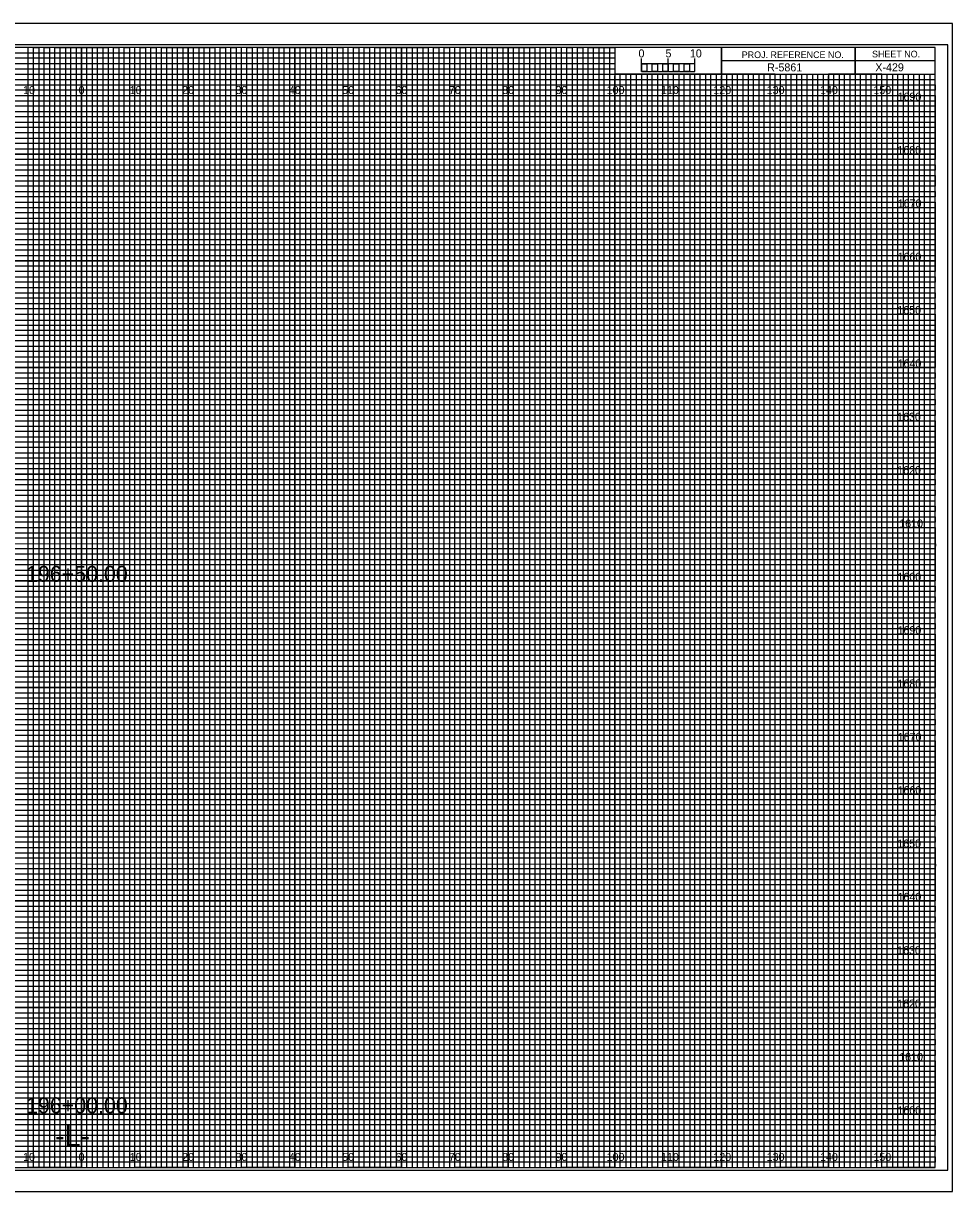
# Model space of a CAD drawing. Extents: x -13 to 323, y -5 to 6154.
# Drawn here: x 149.1 to 323.3, y 5495.5 to 5714.5 of the extents above; entities that cross this region are included whole.
import ezdxf

# ---------------------------------------------------------------- set-up
doc = ezdxf.new("R2010")
doc.units = 0
for name, color, linetype in [('Exist CMT Ground Line', 7, 'Continuous'), ('Prop Horizontal Alignment', 7, 'Continuous'), ('Prop Retaining Wall', 7, 'Continuous'), ('Prop XS Alignment Label', 7, 'Continuous'), ('Prop XS Bar Scale Labels', 7, 'Continuous'), ('Prop XS DDE', 7, 'Continuous'), ('Prop XS DDE Elevations', 7, 'Continuous'), ('Prop XS DDE Slope Text', 7, 'Continuous'), ('Prop XS Earthwork Shape', 7, 'Continuous'), ('Prop XS Elevation Labels', 7, 'Continuous'), ('Prop XS Project Number', 7, 'Continuous'), ('Prop XS Sheet Number', 7, 'Continuous'), ('Prop XS Station Labels', 7, 'Continuous'), ('Raster_Level_0', 7, 'Continuous'), ('Scratch_Level_3', 7, 'Continuous'), ('Sheet Cutting Line CELL', 7, 'Continuous')]:
    doc.layers.add(name, color=color, linetype=linetype)

msp = doc.modelspace()

# ---------------------------------------------------------------- linework, layer by layer
at = {"layer": 'Exist CMT Ground Line'}
for p, q in [((265, 5705.49), (265, 5707.9)), ((265, 5706.9), (265, 5707.9)), ((270, 5705.49), (270, 5707.9)), ((275, 5705.49), (275, 5707.9)), ((275, 5706.9), (275, 5707.9))]:
    msp.add_line(p, q, dxfattribs=at)
for points in [[(275, 5706.9), (265, 5706.9), (265, 5705.49), (275, 5705.49)], [(265, 5706.9), (266, 5706.9), (266, 5705.49), (265, 5705.49)], [(267, 5706.9), (268, 5706.9), (268, 5705.49), (267, 5705.49)], [(269, 5706.9), (270, 5706.9), (270, 5705.49), (269, 5705.49)], [(271, 5706.9), (272, 5706.9), (272, 5705.49), (271, 5705.49)], [(273, 5706.9), (274, 5706.9), (274, 5705.49), (273, 5705.49)]]:
    msp.add_lwpolyline(points, close=True, dxfattribs=at)
at = {"layer": 'Prop Retaining Wall'}
for p, q in [((0, 5709), (260, 5709)), ((260, 5707.98), (0, 5707.98)), ((260, 5709), (260, 5707.98)), ((0, 5707), (260, 5707)), ((260, 5705.89), (0, 5705.89)), ((260, 5707), (260, 5705.89)), ((0, 5704), (320, 5704))]:
    msp.add_line(p, q, dxfattribs=at)
for points in [[(0, 5703), (270, 5703), (320, 5703), (320, 5702), (0, 5702)], [(0, 5701), (320, 5701), (320, 5699), (0, 5699)], [(0, 5698), (320, 5698), (320, 5697), (0, 5696.98)], [(0, 5696), (320, 5696), (320, 5694), (0, 5694)], [(0, 5693), (320, 5693), (320, 5692), (0, 5692)], [(0, 5691), (320, 5691), (320, 5689), (0, 5689)], [(0, 5688), (320, 5688), (320, 5687), (0, 5687)], [(0, 5686), (320, 5686), (320, 5684), (0, 5684)], [(0, 5683), (320, 5683), (320, 5682), (0, 5682)], [(0, 5681), (320, 5681), (320, 5679), (0, 5679)], [(0, 5678), (320, 5678), (320, 5677), (0, 5677)], [(0, 5676), (320, 5676), (320, 5673.95), (320, 5673), (320, 5672), (0, 5672)], [(0, 5674), (320, 5674), (320, 5673), (0, 5673)], [(0, 5671), (320, 5671), (320, 5669), (0, 5669.03)], [(0, 5669.03), (320, 5669), (320, 5668), (0, 5668)], [(0, 5667), (320, 5667), (320, 5666), (0, 5666)], [(0, 5664), (320, 5664), (320, 5663), (0, 5663)], [(0, 5662), (320, 5662), (320, 5661), (0, 5661)], [(-0.07, 5658.89), (320, 5658.89), (320, 5657.88), (-0.07, 5657.88)], [(0, 5657), (320, 5657), (320, 5656), (0, 5656)], [(0, 5654), (320, 5654), (320, 5653), (0, 5653)], [(0, 5652), (320, 5652), (320, 5651), (0, 5651)], [(0, 5649), (320, 5649), (320, 5648), (0, 5648)], [(0, 5647), (320, 5647), (320, 5646), (0, 5646)], [(0, 5644), (320, 5644), (320, 5643), (0, 5643)], [(0, 5642), (320, 5642), (320, 5641), (0, 5641)], [(0, 5639), (320, 5639), (319.99, 5637.98), (0, 5638)], [(0, 5637), (320, 5637), (320, 5636), (0, 5636)], [(0, 5634), (320, 5634), (320, 5633), (0, 5633)], [(0, 5632), (320, 5632), (320, 5631), (0, 5631)], [(0, 5629), (320, 5629), (320, 5628), (0, 5628)], [(0, 5627), (320, 5627), (320, 5626), (0, 5626)], [(0, 5624), (320, 5624), (320, 5623), (0, 5623)], [(0, 5622), (320, 5622), (320, 5621), (0, 5621)], [(0, 5619), (320, 5619), (320, 5618), (0, 5618)], [(0, 5616.99), (320.07, 5616.91), (320, 5616), (0, 5616)], [(0, 5614), (320, 5614), (320, 5613), (0, 5613)], [(0, 5612), (320, 5612), (320, 5611), (0, 5611)], [(0, 5609), (320, 5609), (320, 5608), (0, 5608)], [(0, 5607), (320, 5607), (320, 5606), (0, 5606)], [(0, 5604), (320, 5604), (320, 5603), (0, 5603)], [(0, 5602), (320, 5602), (320, 5601), (0, 5601)], [(0, 5599), (320, 5599), (320, 5598), (0, 5598)], [(0, 5597), (320, 5597), (320, 5596), (0, 5596)], [(0, 5594), (320, 5594), (320, 5593), (0, 5593)], [(0, 5592), (320, 5592), (320, 5591), (0, 5591)], [(0, 5589), (320, 5589), (320, 5588), (0, 5588)], [(0, 5587), (320, 5587), (320, 5586), (0, 5586)], [(0, 5584), (320, 5584), (320, 5583), (0, 5583)], [(0, 5582), (320, 5582), (320, 5581), (0, 5581)], [(0, 5579), (320, 5579), (319.99, 5577.98), (0, 5578)], [(0, 5577), (320, 5577), (320, 5576), (0, 5576)], [(0, 5574), (320, 5574), (320, 5573), (0, 5573)], [(0, 5572), (320, 5572), (320, 5571), (0, 5571)], [(0, 5569), (320, 5569), (320, 5568), (0, 5568)], [(0, 5567), (320, 5567), (320, 5566), (0, 5566)], [(0, 5564), (320, 5564), (320, 5563), (0, 5563)], [(0, 5562), (320, 5562), (320, 5561), (0, 5561)], [(0, 5559), (320, 5559), (320, 5558), (0, 5558)], [(0, 5556.99), (320.07, 5556.91), (320, 5556), (0, 5556)], [(0, 5554), (320, 5554), (320, 5553), (0, 5553)], [(0, 5552), (320, 5552), (320, 5551), (0, 5551)], [(0, 5549), (320, 5549), (320, 5548), (0, 5548)], [(0, 5547), (320, 5547), (320, 5546), (0, 5546)], [(0, 5544), (320, 5544), (320, 5543), (0, 5543)], [(0, 5542), (320, 5542), (320, 5541), (0, 5541)], [(0, 5539), (320, 5539), (320, 5538), (0, 5538)], [(0, 5537), (320, 5537), (320, 5536), (0, 5536)], [(0, 5534), (320, 5534), (320, 5533), (0, 5533)], [(0, 5532), (320, 5532), (320, 5531), (0, 5531)], [(0, 5529), (320, 5529), (320, 5528), (0, 5528)], [(0, 5527), (320, 5527), (320, 5526), (0, 5526)], [(0, 5524), (320, 5524), (320, 5523), (0, 5523)], [(0, 5522), (320, 5522), (320, 5521), (0, 5521)], [(0, 5519), (320, 5519), (320, 5518), (0, 5518)], [(0, 5517), (320, 5517), (320, 5516), (0, 5516)], [(0, 5514), (320, 5514), (320, 5513), (0, 5513)], [(0, 5512), (320, 5512), (320, 5511), (0, 5511)], [(0, 5509), (320, 5509), (320, 5508), (0, 5508)], [(0, 5507), (320, 5507), (320, 5506), (0, 5506)], [(0, 5504), (320, 5504), (320, 5503), (0, 5503)], [(0, 5502), (320, 5502), (320, 5501), (0, 5501)]]:
    msp.add_lwpolyline(points, dxfattribs=at)
at = {"layer": 'Prop XS Alignment Label'}
for p, q in [((305, 5710), (305, 5705)), ((305, 5705), (305, 5710)), ((280, 5707.5), (280, 5705)), ((320, 5707.49), (280, 5707.49)), ((280, 5705), (320, 5705))]:
    msp.add_line(p, q, dxfattribs=at)
for points in [[(320, 5710), (0, 5710), (0, 5500), (320, 5500)], [(280, 5710), (260, 5710), (260, 5705.03), (280, 5705.03)], [(320, 5710), (280, 5710), (280, 5705), (320, 5705)]]:
    msp.add_lwpolyline(points, close=True, dxfattribs=at)
at = {"layer": 'Prop XS DDE'}
msp.add_lwpolyline([(-13.4, 5495.5), (323.3, 5495.5), (323.3, 5714.5), (-13.4, 5714.5)], close=True, dxfattribs=at)
at = {"layer": 'Prop XS DDE Elevations'}
for p, q in [((150, 5500), (150, 5710)), ((160, 5500), (160, 5710)), ((170, 5500), (170, 5710)), ((180, 5500), (180, 5710)), ((190, 5500), (190, 5710)), ((200, 5500), (200, 5710)), ((210, 5500), (210, 5710)), ((220, 5500), (220, 5710)), ((230, 5500), (230, 5710)), ((240, 5500), (240, 5710)), ((250, 5500), (250, 5710)), ((260, 5500), (260, 5704.69)), ((270, 5500), (270, 5704.69)), ((280, 5500), (280, 5704.69)), ((290, 5500), (290, 5704.69)), ((300, 5500), (300, 5704.69)), ((310, 5500), (310, 5704.69)), ((0, 5700), (320, 5700)), ((0, 5690), (320, 5690)), ((0, 5680), (320, 5680)), ((0, 5670), (320, 5670)), ((0, 5660), (320, 5660)), ((0, 5650), (320, 5650)), ((0, 5640), (320, 5640)), ((0, 5630), (320, 5630)), ((0, 5620), (320, 5620)), ((0, 5610), (320, 5610)), ((0, 5600), (320, 5600)), ((0, 5590), (320, 5590)), ((0, 5580), (320, 5580)), ((0, 5570), (320, 5570)), ((0, 5560), (320, 5560)), ((0, 5550), (320, 5550)), ((0, 5540), (320, 5540)), ((0, 5530), (320, 5530)), ((0, 5520), (320, 5520)), ((0, 5510), (320, 5510))]:
    msp.add_line(p, q, dxfattribs=at)
at = {"layer": 'Prop XS DDE Slope Text'}
msp.add_lwpolyline([(-10.8, 5499.5), (322.4, 5499.5), (322.4, 5710.5), (-10.8, 5710.5)], close=True, dxfattribs=at)
at = {"layer": 'Prop XS Earthwork Shape'}
for p, q in [((150, 5710), (140, 5710)), ((150, 5500), (150, 5710)), ((170, 5710), (160, 5710)), ((160, 5710), (160, 5500)), ((170, 5500), (170, 5710)), ((190, 5710), (180, 5710)), ((180, 5710), (180, 5500)), ((190, 5500), (190, 5710)), ((210, 5710), (200, 5710)), ((200, 5710), (200, 5500)), ((210, 5500), (210, 5710)), ((230, 5710), (220, 5710)), ((220, 5710), (220, 5500)), ((230, 5500), (230, 5710)), ((250, 5710), (240, 5710)), ((240, 5710), (240, 5500)), ((250, 5500), (250, 5710)), ((260, 5710), (260, 5500)), ((270, 5500), (270, 5705)), ((290, 5705), (280, 5705)), ((280, 5705), (280, 5500)), ((290, 5500), (290, 5705)), ((310, 5705), (300, 5705)), ((300, 5705), (300, 5500)), ((310, 5500), (310, 5705)), ((160, 5500), (150, 5500)), ((180, 5500), (170, 5500)), ((200, 5500), (190, 5500)), ((220, 5500), (210, 5500)), ((240, 5500), (230, 5500)), ((260, 5500), (250, 5500)), ((280, 5500), (270, 5500)), ((300, 5500), (290, 5500)), ((320, 5500), (310, 5500)), ((320, 5500), (320, 5500))]:
    msp.add_line(p, q, dxfattribs=at)
for points in [[(0, 5700), (320, 5700), (320, 5690), (0, 5690)], [(0, 5680), (320, 5680), (320, 5670), (0, 5670)], [(0, 5660), (320, 5660), (320, 5650), (0, 5650)], [(0, 5640), (320, 5640), (320, 5630), (0, 5630)], [(0, 5620), (320, 5620), (320, 5610), (0, 5610)], [(0, 5600), (320, 5600), (320, 5590), (0, 5590)], [(0, 5580), (320, 5580), (320, 5570), (0, 5570)], [(0, 5560), (320, 5560), (320, 5550), (0, 5550)], [(0, 5540), (320, 5540), (320, 5530), (0, 5530)], [(0, 5520), (320, 5520), (320, 5510), (0, 5510)]]:
    msp.add_lwpolyline(points, dxfattribs=at)
at = {"layer": 'Prop XS Elevation Labels'}
for p, q in [((267, 5705), (266.01, 5705)), ((266.01, 5705), (266.01, 5500)), ((267, 5500), (267, 5705)), ((269, 5705), (268, 5705)), ((268, 5705), (268, 5500)), ((269, 5500), (269, 5705)), ((266.01, 5500), (265, 5500)), ((268, 5500), (267, 5500))]:
    msp.add_line(p, q, dxfattribs=at)
for points in [[(150, 5500), (151, 5500), (151, 5710), (152, 5710), (152, 5500)], [(152, 5500), (153, 5500), (153, 5710), (154, 5710), (154, 5500)], [(155, 5500), (156, 5500), (156, 5710), (157, 5710), (157, 5500)], [(157, 5500), (158, 5500), (158, 5710), (159, 5710), (159, 5500)], [(160, 5500), (161, 5500), (161, 5710), (162, 5710), (162, 5500)], [(162, 5500), (163, 5500), (163, 5710), (164, 5710), (164, 5500)], [(165, 5500), (166, 5500), (166, 5710), (167, 5710), (167, 5500)], [(167, 5500), (168, 5500), (168, 5710), (169, 5710), (169, 5500)], [(170, 5500), (171, 5500), (171, 5710), (172, 5710), (172, 5500)], [(172, 5500), (173, 5500), (173, 5710), (174, 5710), (174, 5500)], [(175, 5500), (176, 5500), (176, 5710), (177, 5710), (177, 5500)], [(177, 5500), (178, 5500), (178, 5710), (179, 5710), (179, 5500)], [(180, 5500), (181, 5500), (181, 5710), (182, 5710), (182, 5500)], [(182, 5500), (183, 5500), (183, 5710), (184, 5710), (184, 5500)], [(185, 5500), (186, 5500), (186, 5710), (187, 5710), (187, 5500)], [(187, 5500), (188, 5500), (188, 5710), (189, 5710), (189, 5500)], [(190, 5500), (191, 5500), (191, 5710), (192, 5710), (192, 5500)], [(192, 5500), (193, 5500), (193, 5710), (194, 5710), (194, 5500)], [(195, 5500), (196, 5500), (196, 5710), (197, 5710), (197, 5500)], [(197, 5500), (198, 5500), (198, 5710), (199, 5710), (199, 5500)], [(200, 5500), (201, 5500), (201, 5710), (202, 5710), (202, 5500)], [(202, 5500), (203, 5500), (203, 5710), (204, 5710), (204, 5500)], [(205, 5500), (206, 5500), (206, 5710), (207, 5710), (207, 5500)], [(207, 5500), (208, 5500), (208, 5710), (209, 5710), (209, 5500)], [(210, 5500), (211, 5500), (211, 5710), (212, 5710), (212, 5500)], [(212, 5500), (213, 5500), (213, 5710), (214, 5710), (214, 5500)], [(215, 5500), (216, 5500), (216, 5710), (217, 5710), (217, 5500)], [(217, 5500), (218, 5500), (218, 5710), (219, 5710), (219, 5500)], [(220, 5500), (221, 5500), (221, 5710), (222, 5710), (222, 5500)], [(222, 5500), (223, 5500), (223, 5710), (224, 5710), (224, 5500)], [(225, 5500), (226, 5500), (226, 5710), (227, 5710), (227, 5500)], [(227, 5500), (228, 5500), (228, 5710), (229, 5710), (229, 5500)], [(230, 5500), (231, 5500), (231, 5710), (232, 5710), (232, 5500)], [(232, 5500), (233, 5500), (233, 5710), (234, 5710), (234, 5500)], [(235, 5500), (236, 5500), (236, 5710), (237, 5710), (237, 5500)], [(237, 5500), (238, 5500), (238, 5710), (239, 5710), (239, 5500)], [(240, 5500), (241, 5500), (241, 5710), (242, 5710), (242, 5500)], [(242, 5500), (243, 5500), (243, 5710), (244, 5710), (244, 5500)], [(245, 5500), (246, 5500), (246, 5710), (247, 5710), (247, 5500)], [(247, 5500), (248, 5500), (248, 5710), (249, 5710), (249, 5500)], [(250, 5500), (251, 5500), (251, 5710), (252, 5710), (252, 5500)], [(252, 5500), (253, 5500), (253, 5710), (254, 5710), (254, 5500)], [(255, 5500), (256, 5500), (256, 5710), (257, 5710), (257, 5500)], [(257, 5500), (258, 5500), (258, 5710), (259, 5710), (259, 5500)], [(260, 5500), (261, 5500), (261, 5705), (262.02, 5705), (262.02, 5500)], [(262, 5500), (263, 5500), (263, 5705), (263.99, 5705), (263.99, 5500)], [(270, 5500), (270.98, 5500), (270.98, 5705), (272, 5705), (272, 5500)], [(272, 5500), (273, 5500), (273, 5705), (274.05, 5705), (274.05, 5500)], [(275, 5500), (276, 5500), (276, 5705), (277, 5705), (277, 5500)], [(277, 5500), (278, 5500), (278, 5705), (279, 5705), (279, 5500)], [(280, 5500), (281, 5500), (281, 5705), (282, 5705), (282, 5500)], [(282, 5500), (283, 5500), (283, 5705), (284, 5705), (284, 5500)], [(285, 5500), (286, 5500), (286, 5705), (287, 5705), (287, 5500)], [(287, 5500), (288, 5500), (288, 5705), (289, 5705), (289, 5500)], [(290, 5500), (291, 5500), (291, 5705), (292, 5705), (292, 5500)], [(292, 5500), (293, 5500), (293, 5705), (294, 5705), (294, 5500)], [(295, 5500), (296, 5500), (296, 5705), (297, 5705), (297, 5500)], [(297, 5500), (298, 5500), (298, 5705), (299, 5705), (299, 5500)], [(300, 5500), (301, 5500), (301, 5705), (302, 5705), (302, 5500)], [(302, 5500), (303, 5500), (303, 5705), (304, 5705), (304, 5500)], [(305, 5500), (306, 5500), (306, 5705), (307, 5705), (307, 5500)], [(307, 5500), (308, 5500), (308, 5705), (309, 5705), (309, 5500)], [(310, 5500), (311, 5500), (311, 5705), (312, 5705), (312, 5500)], [(312, 5500), (313, 5500), (313, 5705), (314, 5705), (314, 5500)], [(315, 5500), (316, 5500), (316, 5705), (317, 5705), (317, 5500)], [(317, 5500), (318, 5500), (318, 5705), (319, 5705), (319, 5500)]]:
    msp.add_lwpolyline(points, dxfattribs=at)
at = {"layer": 'Prop XS Station Labels'}
for points in [[(145, 5500), (155, 5500), (155, 5710), (165, 5710), (165, 5500), (175, 5500), (175, 5710), (185, 5710), (185, 5500), (195, 5500), (195, 5710), (205, 5710), (205, 5500), (215, 5500), (215, 5710), (225, 5710), (225, 5500), (235, 5500), (235, 5710), (245, 5710), (245, 5500), (255, 5500), (255, 5710), (259.93, 5710), (260, 5710), (260, 5705), (264.99, 5705), (264.99, 5500), (275, 5500), (275, 5705), (285, 5705), (285, 5500), (295, 5500), (295, 5705), (305, 5705), (305, 5500), (315, 5500), (315, 5705)], [(0, 5705), (275, 5705)], [(0, 5685), (320, 5685), (320, 5695), (0, 5695)], [(0, 5665), (320, 5665), (320, 5675), (0, 5675)], [(0, 5645), (320, 5645), (320, 5655), (0, 5655)], [(0, 5625), (320, 5625), (320, 5635), (0, 5635)], [(0, 5605), (320, 5605), (320, 5615), (0, 5615)], [(0, 5585), (320, 5585), (320, 5595), (0, 5595)], [(0, 5565), (320, 5565), (320, 5575), (0, 5575)], [(0, 5545), (320, 5545), (320, 5555), (0, 5555)], [(0, 5525), (320, 5525), (320, 5535), (0, 5535)], [(0, 5505), (320, 5505), (320, 5515), (0, 5515)]]:
    msp.add_lwpolyline(points, dxfattribs=at)
at = {"layer": 'Sheet Cutting Line CELL'}
for p, q in [((323.3, 5714.5), (-13.4, 5714.5)), ((-13.4, 5495.5), (323.3, 5495.5))]:
    msp.add_line(p, q, dxfattribs=at)

# ---------------------------------------------------------------- texts
at = {"layer": 'Exist CMT Ground Line'}
msp.add_text('0', height=1.5, dxfattribs=at).set_placement((264.41, 5708.12))
at = {"layer": 'Prop Horizontal Alignment'}
for s, p in [('196+50.00', (149.59, 5609.8)), ('196+00.00', (149.59, 5510.18))]:
    msp.add_text(s, height=3, dxfattribs=at).set_placement(p)
at = {"layer": 'Prop XS Alignment Label'}
for s, height, p in [('SHEET NO.', 1.25, (308.19, 5708.12)), ('PROJ. REFERENCE NO.', 1.25, (283.77, 5707.99)), ('-L-', 4, (155.06, 5504))]:
    msp.add_text(s, height=height, dxfattribs=at).set_placement(p)
at = {"layer": 'Prop XS Bar Scale Labels'}
for s, p in [('5', (269.47, 5708.12)), ('10', (274.04, 5708.12))]:
    msp.add_text(s, height=1.5, dxfattribs=at).set_placement(p)
at = {"layer": 'Prop XS Project Number'}
msp.add_text('R-5861', height=1.5, dxfattribs=at).set_placement((288.53, 5705.5))
at = {"layer": 'Prop XS Sheet Number'}
msp.add_text('X-429', height=1.5, dxfattribs=at).set_placement((308.8, 5705.51))
at = {"layer": 'Raster_Level_0'}
for s, p in [('10', (149.04, 5701.25)), ('0', (159.45, 5701.25)), ('0', (159.45, 5701.25)), ('10', (169.04, 5701.25)), ('20', (178.86, 5701.25)), ('30', (188.86, 5701.25)), ('40', (198.86, 5701.25)), ('50', (208.86, 5701.25)), ('60', (218.86, 5701.25)), ('70', (228.86, 5701.25)), ('80', (238.86, 5701.25)), ('90', (248.86, 5701.25)), ('100', (258.44, 5701.25)), ('110', (268.62, 5701.25)), ('120', (278.44, 5701.25)), ('130', (288.44, 5701.25)), ('140', (298.44, 5701.25)), ('150', (308.44, 5701.25)), ('10', (149.04, 5501.25)), ('0', (159.45, 5501.25)), ('0', (159.45, 5501.25)), ('10', (169.04, 5501.25)), ('20', (178.86, 5501.25)), ('30', (188.86, 5501.25)), ('40', (198.86, 5501.25)), ('50', (208.86, 5501.25)), ('60', (218.86, 5501.25)), ('70', (228.86, 5501.25)), ('80', (238.86, 5501.25)), ('90', (248.86, 5501.25)), ('100', (258.44, 5501.25)), ('110', (268.62, 5501.25)), ('120', (278.44, 5501.25)), ('130', (288.44, 5501.25)), ('140', (298.44, 5501.25)), ('150', (308.44, 5501.25))]:
    msp.add_text(s, height=1.5, dxfattribs=at).set_placement(p)
at = {"layer": 'Scratch_Level_3'}
for s, p in [('1690', (312.97, 5700)), ('1680', (312.95, 5690)), ('1670', (313, 5680)), ('1660', (312.97, 5670)), ('1650', (312.92, 5660)), ('1640', (312.97, 5650)), ('1630', (312.89, 5640)), ('1620', (312.9, 5630)), ('1610', (313.28, 5620)), ('1600', (312.95, 5610)), ('1690', (312.97, 5600)), ('1680', (312.95, 5590)), ('1670', (313, 5580)), ('1660', (312.97, 5570)), ('1650', (312.92, 5560)), ('1640', (312.97, 5550)), ('1630', (312.89, 5540)), ('1620', (312.9, 5530)), ('1610', (313.28, 5520)), ('1600', (312.95, 5510))]:
    msp.add_text(s, height=1.5, dxfattribs=at).set_placement(p)

doc.saveas('drawing.dxf')
